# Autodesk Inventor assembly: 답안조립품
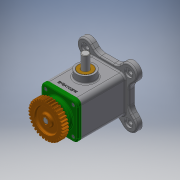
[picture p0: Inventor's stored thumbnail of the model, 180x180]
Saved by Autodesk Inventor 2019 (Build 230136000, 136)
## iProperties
Created: 2021-01
Part Number: 답안조립품
Material: 일반
Document SubType Name: Assembly
Designer: 3DPRO16
Author: 3DPRO16
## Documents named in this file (11)
- C:\Users\3DPRO16\Desktop\710114V1006\710114V1006\답안조립품.iam
- C:\Users\3DPRO16\Desktop\710114V1006\710114V1006\본체.ipt
- C:\Users\3DPRO16\Desktop\710114V1006\710114V1006\베어링 6203.ipt
- C:\Users\3DPRO16\Desktop\710114V1006\710114V1006\볼트 M4.ipt
- C:\Users\3DPRO16\Desktop\710114V1006\710114V1006\부시.ipt
- C:\Users\3DPRO16\Desktop\710114V1006\710114V1006\스퍼기어.ipt
- C:\Users\3DPRO16\Desktop\710114V1006\710114V1006\슬라이더.ipt
- C:\Users\3DPRO16\Desktop\710114V1006\710114V1006\오일 실.ipt
- C:\Users\3DPRO16\Desktop\710114V1006\710114V1006\커버.ipt
- C:\Users\3DPRO16\Desktop\710114V1006\710114V1006\키 4 x 4 x 14.ipt
- C:\Users\3DPRO16\Desktop\710114V1006\710114V1006\편심축.ipt
